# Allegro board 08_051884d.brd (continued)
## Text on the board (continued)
PAGE_OUTLINE: B | C | D | CHANGE PER ECR-084936 | CHANGE PER ECR-096196 | CHANGE PER ECR-113119 | 29JAN20 | 19JUN20 | 20FEB23 | D.J. | P.H. | K.B. | EVALUATION BOARD
User.15: CHARACTERISTIC IMPEDANCE = 50 OHMS DIFF +/- 10% | ARTWORK LINE WIDTH FOR | IMPEDANCE CONTROLLED LINES = 0.030" FOR L1 AND L12 | IMPEDANCE CONTROLLED LINES = 0.0070" FOR L3 AND L10 | DIFFERENTIAL IMPEDANCE = 100 OHMS +/- 10% | IMPEDANCE CONTROLLED LINES = 0.0040" FOR L1 AND L12 | IMPEDANCE CONTROLLED LINES = 0.00525" FOR L3 AND L10 | 0.005" TACHYON | 16.    DUE TO CONGESTION CLIPPING OF SILKSCREEN ALLOWED.
User.17: L2 GROUND | 08-      -07
User.18: L3 SIGNAL | 08-      -08
User.19: L4 GROUND | 08-      -09
User.20: L5 POWER ANALOG | 08-      -10
User.22: L6 GROUND | 08-      -11
User.23: L7 POWER DIGITAL | 08-      -12
User.24: L8 GROUND | 08-      -13
User.25: L9 POWER DVDD1 | 08-      -14
User.26: L10 SIGNAL | 08-      -15
User.27: L11 GROUND | 08-      -16
User.33: (REF) | LAYER 12 TO LAYER 9 DRILLS | LAYER 1 TO LAYER 4 DRILLS | SEE NOTE 15
User.45: FIGURE | SIZE | 8.0 | 6.0 | 10.0 | 12.0 | 16.0 | 20.0 | 40.0 | 50.0 | 75.0 | 105.0 | PLATED | NON-PLATED | FINISHED HOLES IN MILS | ALL UNITS ARE IN MILS | QTY | 1109 | 4 | 867 | 297 | 162 | 72 | 3 | 2 | 837 | TOLERANCE/NOTES
